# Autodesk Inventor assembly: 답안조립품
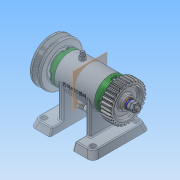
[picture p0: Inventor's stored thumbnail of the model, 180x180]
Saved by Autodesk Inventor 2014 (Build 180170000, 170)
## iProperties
Created: 2016-07
Part Number: 답안조립품
Document SubType Name: Assembly
Designer: net
Author: net
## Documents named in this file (16)
- C:\Users\net\Desktop\460707V1022\답안조립품.iam
- C:\Users\net\Desktop\460707V1022\본체.ipt
- C:\Users\net\Desktop\460707V1022\커버.ipt
- C:\Users\net\Desktop\460707V1022\볼트 M4 x 12.ipt
- C:\Users\net\Desktop\460707V1022\오일 실 15 25 7.ipt
- C:\Users\net\Desktop\460707V1022\축.ipt
- C:\Users\net\Desktop\460707V1022\키 3 x 3 x 12.ipt
- C:\Users\net\Desktop\460707V1022\베어링 15 x 32 x 9.ipt
- C:\Users\net\Desktop\460707V1022\V벨트풀리.ipt
- C:\Users\net\Desktop\460707V1022\스퍼기어.ipt
- C:\Users\net\Desktop\460707V1022\니플 M 6 x 0.75.ipt
- C:\Users\net\Desktop\460707V1022\와셔 6x11.5.ipt
- C:\Users\net\Desktop\460707V1022\볼트 M 6 x 8.ipt
- C:\Users\net\Desktop\460707V1022\와셔 8x17.ipt
- C:\Users\net\Desktop\460707V1022\스프링와셔 8.ipt
- C:\Users\net\Desktop\460707V1022\너트 M 8.ipt
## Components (11 placed, 3 different names)
1. KS B 2023 6002 - 15 x 32 x 9:1
2. KS B 2023 6002 - 15 x 32 x 9:2
3. V벨트풀리:1 — 각도:2
4. ISO 4762 M4 x 12:1
5. ISO 4762 M4 x 12:3
6. ISO 4762 M4 x 12:4
7. ISO 4762 M4 x 12:5
8. ISO 4762 M4 x 12:2
9. ISO 4762 M4 x 12:6
10. ISO 4762 M4 x 12:7
11. ISO 4762 M4 x 12:8
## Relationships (1: Angle 1)
- 각도:2 [Angle]: V벨트풀리:1
